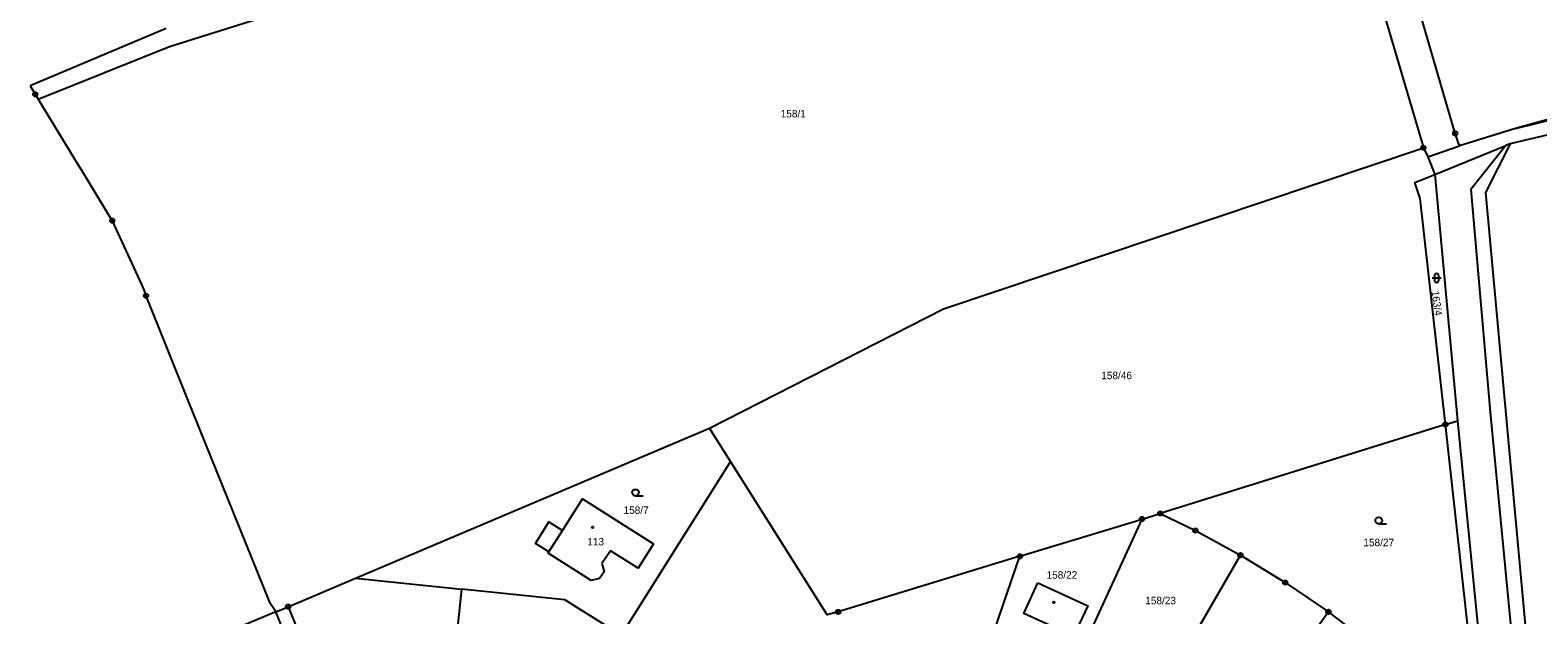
# Model space of a CAD drawing. Extents: x -779723 to -777378, y -1011169 to -1009297.
# Drawn here: x -779564.1 to -779222.9, y -1010012.9 to -1009880.5 of the extents above; entities that cross this region are included whole.
import ezdxf

# ---------------------------------------------------------------- set-up
doc = ezdxf.new("R2010")
doc.units = 0
for name, color, linetype in [('Hranice parcel', 7, 'Continuous'), ('Parcelní čísla', 7, 'Continuous'), ('Vnitřní kresba', 7, 'Continuous'), ('Značky bodu BP', 7, 'Continuous'), ('Značky budov', 7, 'Continuous'), ('Značky kultur', 7, 'Continuous')]:
    doc.layers.add(name, color=color, linetype=linetype)

msp = doc.modelspace()

# ---------------------------------------------------------------- linework, layer by layer
at = {"layer": 'Hranice parcel'}
for p, q in [((-779278.74, -1009805.06), (-779248.82, -1009907.09)), ((-779533.32, -1009880.08), (-779564.1, -1009893.09)), ((-779562.25, -1009896.12), (-779553.96, -1009909.75)), ((-779228.01, -1009902.71), (-779240.66, -1009906.64)), ((-779229.16, -1009906.17), (-779230.18, -1009906.58)), ((-779553.96, -1009909.75), (-779552.25, -1009912.56)), ((-779248.82, -1009907.09), (-779247.8, -1009909.13)), ((-779247.8, -1009909.13), (-779240.66, -1009906.64)), ((-779247.8, -1009909.13), (-779246.23, -1009913.12)), ((-779246.23, -1009913.12), (-779230.18, -1009906.58)), ((-779552.25, -1009912.56), (-779545.52, -1009923.61)), ((-779246.23, -1009913.12), (-779241.08, -1009968.91)), ((-779545.52, -1009923.61), (-779538.94, -1009938.03)), ((-779537.89, -1009940.61), (-779528.57, -1009963.94)), ((-779528.57, -1009963.94), (-779510, -1010009.82)), ((-779490.5, -1010004.56), (-779410.38, -1009970.58)), ((-779405.63, -1009978.11), (-779410.38, -1009970.58)), ((-779243.85, -1009969.77), (-779308.35, -1009989.9)), ((-779243.85, -1009969.77), (-779241.08, -1009968.91)), ((-779238.78, -1010015.64), (-779243.85, -1009969.77)), ((-779405.63, -1009978.11), (-779430.36, -1010017.45)), ((-779340.12, -1009999.61), (-779312.49, -1009991.16)), ((-779326.85, -1010022.6), (-779312.49, -1009991.16)), ((-779312.49, -1009991.16), (-779308.35, -1009989.9)), ((-779309, -1010031.79), (-779290.22, -1009999.35)), ((-779505.72, -1010011.01), (-779490.5, -1010004.56)), ((-779490.5, -1010004.56), (-779466.49, -1010007.04)), ((-779466.49, -1010007.04), (-779471.6, -1010056.37)), ((-779508.48, -1010012.18), (-779505.72, -1010011.01)), ((-779489.42, -1010058.31), (-779508.48, -1010012.18)), ((-779505.72, -1010011.01), (-779486.32, -1010057.97)), ((-779270.32, -1010012.18), (-779292.64, -1010043.39))]:
    msp.add_line(p, q, dxfattribs=at)
for points in [[(-779240.66, -1009906.64), (-779241.62, -1009903.83), (-779272.7, -1009797.05), (-779279.09, -1009775.18)], [(-779562.25, -1009896.12), (-779532.56, -1009884.15), (-779506.87, -1009876.1), (-779472.82, -1009867.46), (-779457.86, -1009862.77), (-779428.56, -1009854.48), (-779394.15, -1009837.46)], [(-779100.65, -1009884.22), (-779103.85, -1009880.84), (-779153.46, -1009883.76), (-779161.05, -1009884.21), (-779228.01, -1009902.71)], [(-779228.01, -1009902.71), (-779160.94, -1009886.18), (-779100.65, -1009884.22)], [(-779104.09, -1009887.32), (-779157.23, -1009889.11), (-779229.16, -1009906.17)], [(-779564.1, -1009893.09), (-779562.94, -1009894.99), (-779562.25, -1009896.12)], [(-779229.16, -1009906.17), (-779234.8, -1009917.25), (-779223.59, -1010039.03), (-779218.82, -1010085.26), (-779212.16, -1010143.8)], [(-779410.38, -1009970.58), (-779357.43, -1009943.56), (-779248.82, -1009907.09)], [(-779230.18, -1009906.58), (-779238.1, -1009916.55), (-779233.71, -1009966.95), (-779226.79, -1010039.25), (-779219.75, -1010106.05), (-779218.61, -1010144.17)], [(-779243.85, -1009969.77), (-779249.52, -1009918.58), (-779250.74, -1009914.96), (-779246.23, -1009913.12)], [(-779538.94, -1009938.03), (-779538.37, -1009939.28), (-779537.89, -1009940.61)], [(-779241.08, -1009968.91), (-779234.07, -1010040.11), (-779233.9, -1010041.71)], [(-779340.12, -1009999.61), (-779381.24, -1010012.19), (-779383.71, -1010012.84), (-779405.63, -1009978.11)], [(-779434.71, -1010001.23), (-779434.23, -1010003.15), (-779435.26, -1010004.63), (-779437.12, -1010005.06), (-779446.86, -1009998.86), (-779446.7, -1009998.61), (-779449.77, -1009996.67), (-779446.72, -1009991.8), (-779443.63, -1009993.74), (-779439.14, -1009986.62), (-779423.07, -1009996.75), (-779426.49, -1010002.32), (-779432.77, -1009998.38), (-779434.71, -1010001.23)], [(-779308.35, -1009989.9), (-779300.4, -1009993.78), (-779290.22, -1009999.35)], [(-779326.85, -1010022.6), (-779333.1, -1010020.18), (-779339.43, -1010018.09), (-779345.89, -1010016.32), (-779340.12, -1009999.61)], [(-779290.22, -1009999.35), (-779280.07, -1010005.56), (-779270.32, -1010012.18)], [(-779430.36, -1010017.45), (-779443.07, -1010009.46), (-779466.49, -1010007.04)], [(-779336.09, -1010005.63), (-779324.79, -1010010.8), (-779327.97, -1010017.71), (-779339.22, -1010012.55), (-779336.09, -1010005.63)], [(-779508.48, -1010012.18), (-779509.9, -1010012.78), (-779522.9, -1010018.23)], [(-779510, -1010009.82), (-779508.57, -1010011.97), (-779508.48, -1010012.18)], [(-779250.57, -1010027.88), (-779260.26, -1010019.77), (-779270.32, -1010012.18)]]:
    msp.add_lwpolyline(points, dxfattribs=at)
at = {"layer": 'Vnitřní kresba'}
msp.add_line((-779446.7, -1009998.61), (-779443.63, -1009993.74), dxfattribs=at)
at = {"layer": 'Značky bodu BP'}
for centre, radius in [((-779562.94, -1009894.99), 0.5), ((-779562.94, -1009894.99), 0.0303), ((-779241.62, -1009903.83), 0.5), ((-779241.62, -1009903.83), 0.0303), ((-779248.82, -1009907.09), 0.5), ((-779248.82, -1009907.09), 0.0303), ((-779545.52, -1009923.61), 0.5), ((-779545.52, -1009923.61), 0.0303), ((-779537.89, -1009940.61), 0.5), ((-779537.89, -1009940.61), 0.0303), ((-779243.85, -1009969.77), 0.5), ((-779243.85, -1009969.77), 0.0303), ((-779312.49, -1009991.16), 0.5), ((-779312.49, -1009991.16), 0.0303), ((-779308.35, -1009989.9), 0.5), ((-779308.35, -1009989.9), 0.0303), ((-779300.4, -1009993.78), 0.5), ((-779300.4, -1009993.78), 0.0303), ((-779340.12, -1009999.61), 0.5), ((-779340.12, -1009999.61), 0.0303), ((-779290.22, -1009999.35), 0.5), ((-779290.22, -1009999.35), 0.0303), ((-779280.07, -1010005.56), 0.5), ((-779280.07, -1010005.56), 0.0303), ((-779505.72, -1010011.01), 0.5), ((-779505.72, -1010011.01), 0.0303), ((-779381.24, -1010012.19), 0.5), ((-779381.24, -1010012.19), 0.0303), ((-779270.32, -1010012.18), 0.5), ((-779270.32, -1010012.18), 0.0303)]:
    msp.add_circle(centre, radius, dxfattribs=at)
at = {"layer": 'Značky budov'}
for centre in [(-779436.79, -1009993.04), (-779332.45, -1010010.02)]:
    msp.add_circle(centre, 0.175, dxfattribs=at)
at = {"layer": 'Značky kultur'}
for p, q in [((-779246.83, -1009936.58), (-779244.83, -1009936.58)), ((-779246.33, -1009936.08), (-779246.33, -1009937.08)), ((-779245.33, -1009937.08), (-779245.33, -1009936.08)), ((-779427.11, -1009985.94), (-779425.36, -1009985.94)), ((-779258.93, -1009992.24), (-779257.18, -1009992.24))]:
    msp.add_line(p, q, dxfattribs=at)
for centre in [(-779427.11, -1009985.19), (-779258.93, -1009991.49)]:
    msp.add_circle(centre, 0.75, dxfattribs=at)
for centre, start, end in [((-779245.83, -1009936.08), 0, 180), ((-779245.83, -1009937.08), 180, 359.9879)]:
    msp.add_arc(centre, 0.5, start, end, dxfattribs=at)

# ---------------------------------------------------------------- texts
at = {"layer": 'Parcelní čísla'}
for s, p in [('158/1', (-779394.25, -1009900.23)), ('158/46', (-779321.72, -1009959.5)), ('158/7', (-779429.82, -1009990)), ('113', (-779438.03, -1009997.14)), ('158/27', (-779262.4, -1009997.32)), ('158/22', (-779334.1, -1010004.67)), ('158/23', (-779311.76, -1010010.47))]:
    msp.add_text(s, height=1.7, dxfattribs=at).set_placement(p)
msp.add_text('163/4', height=1.7, rotation=278, dxfattribs=at).set_placement((-779247.01, -1009939.59))

doc.saveas('drawing.dxf')
